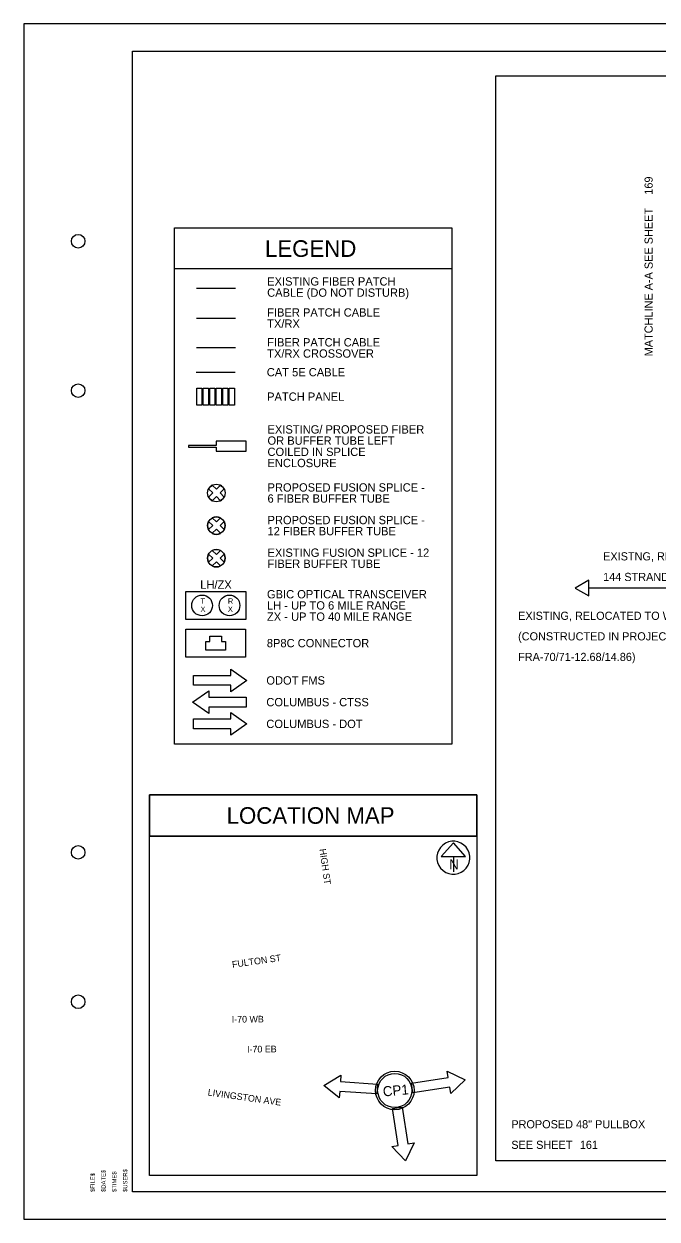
# Model space of a CAD drawing. Extents: x 1805893 to 1833564, y 708898 to 716199.
# Drawn here: x 1832103.1 to 1832336.4, y 713757.9 to 714197.9 of the extents above; entities that cross this region are included whole.
import ezdxf

# ---------------------------------------------------------------- set-up
doc = ezdxf.new("R2010")
doc.units = 0
for name, color, linetype in [('BR_P_Sub_Hidden', 7, 'Continuous'), ('BR_X_Slab_Object', 7, 'Continuous'), ('SH_Border', 7, 'Continuous'), ('SH_Cut_Line', 7, 'Continuous'), ('SH_Data', 7, 'Continuous'), ('SH_Text', 7, 'Continuous'), ('UT_X_Misc_Cells', 7, 'Continuous')]:
    doc.layers.add(name, color=color, linetype=linetype)

msp = doc.modelspace()

# ---------------------------------------------------------------- linework, layer by layer
at = {"layer": 'BR_P_Sub_Hidden'}
msp.add_lwpolyline([(1832277.01, 714178.75), (1832747.57, 714178.75), (1832747.57, 713779.36), (1832277.01, 713779.36)], close=True, dxfattribs=at)
at = {"layer": 'SH_Border'}
msp.add_lwpolyline([(1832143.13, 714187.91), (1832773.13, 714187.91), (1832773.13, 713767.91), (1832143.13, 713767.91)], close=True, dxfattribs=at)
for centre in [(1832123.13, 714117.91), (1832123.13, 714062.91), (1832123.13, 713892.91), (1832123.13, 713837.91)]:
    msp.add_circle(centre, 2.5, dxfattribs=at)
at = {"layer": 'SH_Cut_Line'}
msp.add_lwpolyline([(1832103.13, 713757.91), (1832783.13, 713757.91), (1832783.13, 714197.91), (1832103.13, 714197.91)], close=True, dxfattribs=at)
at = {"layer": 'SH_Data'}
for p, q in [((1832166.73, 714100.63), (1832181.07, 714100.63)), ((1832166.73, 714089.63), (1832181.07, 714089.63)), ((1832174.03, 714026.58), (1832172.54, 714028.08)), ((1832174.03, 714026.58), (1832172.54, 714028.08)), ((1832174.03, 714026.58), (1832175.53, 714028.08)), ((1832175.53, 714028.08), (1832174.03, 714026.58)), ((1832172.68, 714025.23), (1832171.19, 714026.72)), ((1832171.19, 714026.72), (1832172.68, 714025.23)), ((1832171.19, 714023.74), (1832172.68, 714025.23)), ((1832172.68, 714025.23), (1832171.19, 714023.74)), ((1832172.54, 714022.38), (1832174.03, 714023.87)), ((1832172.54, 714022.38), (1832174.03, 714023.87)), ((1832175.53, 714022.38), (1832174.03, 714023.87)), ((1832174.03, 714023.87), (1832175.53, 714022.38)), ((1832175.39, 714025.23), (1832176.88, 714026.72)), ((1832175.39, 714025.23), (1832176.88, 714026.72)), ((1832176.88, 714023.74), (1832175.39, 714025.23)), ((1832176.88, 714023.74), (1832175.39, 714025.23)), ((1832172.68, 714013.22), (1832171.19, 714014.71)), ((1832172.68, 714013.22), (1832171.19, 714014.71)), ((1832174.03, 714014.57), (1832172.54, 714016.07)), ((1832172.54, 714016.07), (1832174.03, 714014.57)), ((1832174.03, 714014.57), (1832175.53, 714016.07)), ((1832174.03, 714014.57), (1832175.53, 714016.07)), ((1832175.39, 714013.22), (1832176.88, 714014.71)), ((1832176.88, 714014.71), (1832175.39, 714013.22)), ((1832171.19, 714011.73), (1832172.68, 714013.22)), ((1832171.19, 714011.73), (1832172.68, 714013.22)), ((1832172.54, 714010.37), (1832174.03, 714011.86)), ((1832174.03, 714011.86), (1832172.54, 714010.37)), ((1832175.53, 714010.37), (1832174.03, 714011.86)), ((1832175.53, 714010.37), (1832174.03, 714011.86)), ((1832176.88, 714011.73), (1832175.39, 714013.22)), ((1832175.39, 714013.22), (1832176.88, 714011.73)), ((1832172.68, 714001.21), (1832171.19, 714002.71)), ((1832172.68, 714001.21), (1832171.19, 714002.71)), ((1832171.19, 713999.72), (1832172.68, 714001.21)), ((1832171.19, 713999.72), (1832172.68, 714001.21)), ((1832174.03, 714002.57), (1832172.54, 714004.06)), ((1832172.54, 714004.06), (1832174.03, 714002.57)), ((1832174.03, 714002.57), (1832175.53, 714004.06)), ((1832174.03, 714002.57), (1832175.53, 714004.06)), ((1832175.39, 714001.21), (1832176.88, 714002.71)), ((1832176.88, 714002.71), (1832175.39, 714001.21)), ((1832176.88, 713999.72), (1832175.39, 714001.21)), ((1832175.39, 714001.21), (1832176.88, 713999.72)), ((1832172.54, 713998.37), (1832174.03, 713999.86)), ((1832174.03, 713999.86), (1832172.54, 713998.37)), ((1832175.53, 713998.37), (1832174.03, 713999.86)), ((1832175.53, 713998.37), (1832174.03, 713999.86)), ((1832311.2, 713993.13), (1832306.18, 713990.23)), ((1832311.2, 713987.33), (1832311.2, 713993.13)), ((1832306.18, 713990.23), (1832311.2, 713987.33)), ((1832363.68, 713990.23), (1832311.2, 713990.23)), ((1832165.58, 713958.02), (1832179.31, 713958.02)), ((1832165.58, 713954.42), (1832165.58, 713958.02)), ((1832179.31, 713958.02), (1832179.31, 713960.42)), ((1832179.31, 713954.42), (1832165.58, 713954.42)), ((1832179.31, 713952.02), (1832179.31, 713954.42)), ((1832171.24, 713952.42), (1832171.24, 713950.02)), ((1832171.24, 713950.02), (1832184.98, 713950.02)), ((1832184.98, 713950.02), (1832184.98, 713946.42)), ((1832184.98, 713946.42), (1832171.24, 713946.42)), ((1832171.24, 713946.42), (1832171.24, 713944.02)), ((1832179.31, 713942.02), (1832179.31, 713944.42)), ((1832165.58, 713942.02), (1832179.31, 713942.02)), ((1832165.58, 713938.42), (1832165.58, 713942.02)), ((1832179.31, 713938.42), (1832165.58, 713938.42)), ((1832179.31, 713936.02), (1832179.31, 713938.42))]:
    msp.add_line(p, q, dxfattribs=at)
for points in [[(1832158.57, 714122.86), (1832260.8, 714122.86), (1832260.8, 714107.75), (1832158.57, 714107.75)], [(1832260.8, 714122.86), (1832260.8, 713932.7), (1832158.57, 713932.7), (1832158.57, 714122.86)], [(1832168.74, 714063.81), (1832168.74, 714057.56), (1832166.78, 714057.56), (1832166.78, 714063.81)], [(1832171.14, 714063.81), (1832171.14, 714057.56), (1832169.18, 714057.56), (1832169.18, 714063.81)], [(1832173.53, 714063.81), (1832173.53, 714057.56), (1832171.57, 714057.56), (1832171.57, 714063.81)], [(1832175.93, 714063.81), (1832175.93, 714057.56), (1832173.97, 714057.56), (1832173.97, 714063.81)], [(1832178.32, 714063.81), (1832178.32, 714057.56), (1832176.36, 714057.56), (1832176.36, 714063.81)], [(1832180.72, 714063.81), (1832180.72, 714057.56), (1832178.76, 714057.56), (1832178.76, 714063.81)], [(1832162.78, 713988.95), (1832184.88, 713988.95), (1832184.88, 713978.7), (1832162.78, 713978.7)], [(1832162.73, 713975.07), (1832184.82, 713975.07), (1832184.82, 713964.82), (1832162.73, 713964.82)], [(1832270.01, 713914.04), (1832149.37, 713914.04), (1832149.37, 713898.93), (1832270.01, 713898.93)], [(1832270.01, 713898.93), (1832149.37, 713898.93), (1832149.37, 713914.04), (1832270.01, 713914.04)], [(1832270.01, 713898.93), (1832270.01, 713773.91), (1832149.37, 713773.91), (1832149.37, 713898.93)], [(1832270.01, 713898.93), (1832270.01, 713773.91), (1832149.37, 713773.91), (1832149.37, 713898.93)], [(1832270.01, 713898.93), (1832270.01, 713773.91), (1832149.37, 713773.91), (1832149.37, 713898.93)]]:
    msp.add_lwpolyline(points, close=True, dxfattribs=at)
for points in [[(1832181.1, 714078.63), (1832166.73, 714078.63), (1832166.73, 714078.63), (1832166.73, 714078.63)], [(1832166.6, 714069.69), (1832180.94, 714069.72), (1832180.94, 714069.72)], [(1832163.74, 714042.75), (1832163.74, 714042.45), (1832163.74, 714042.14), (1832174.02, 714042.14), (1832174.02, 714040.61), (1832185.07, 714040.61), (1832185.07, 714044.28), (1832174.02, 714044.28), (1832174.02, 714042.75), (1832163.74, 714042.75)], [(1832185.07, 714040.61), (1832185.07, 714044.28), (1832174.02, 714044.28), (1832174.02, 714042.75), (1832163.74, 714042.75), (1832163.74, 714042.45), (1832163.74, 714042.14), (1832174.02, 714042.14), (1832174.02, 714040.61), (1832185.07, 714040.61)], [(1832175.9, 713970.55), (1832177.41, 713970.55), (1832177.41, 713967.32), (1832170.14, 713967.32), (1832170.14, 713970.55), (1832171.65, 713970.55)], [(1832171.65, 713970.55), (1832171.65, 713972.46), (1832175.9, 713972.46), (1832175.9, 713970.55)], [(1832179.31, 713960.42), (1832185.31, 713956.22), (1832179.31, 713952.02)], [(1832171.24, 713944.02), (1832165.24, 713948.22), (1832171.24, 713952.42)], [(1832179.31, 713944.42), (1832185.31, 713940.22), (1832179.31, 713936.02)]]:
    msp.add_lwpolyline(points, dxfattribs=at)
for centre, radius in [((1832174.03, 714025.23), 3.22), ((1832174.03, 714013.22), 3.22), ((1832174.03, 714001.21), 3.22), ((1832168.78, 713983.83), 3.81), ((1832178.88, 713983.83), 3.81)]:
    msp.add_circle(centre, radius, dxfattribs=at)
for centre, start, end in [((1832174.03, 714025.23), 117.647, 152.353), ((1832174.03, 714025.23), 27.647, 62.353), ((1832174.03, 714025.23), 207.647, 242.353), ((1832174.03, 714025.23), 297.647, 332.353), ((1832174.03, 714013.22), 152.353, 207.647), ((1832174.03, 714013.22), 62.353, 117.647), ((1832174.03, 714013.22), 332.353, 27.647), ((1832174.03, 714013.22), 242.353, 297.647), ((1832174.03, 714001.21), 152.353, 207.647), ((1832174.03, 714001.21), 62.353, 117.647), ((1832174.03, 714001.21), 332.353, 27.647), ((1832174.03, 714001.21), 242.353, 297.647)]:
    msp.add_arc(centre, 3.22, start, end, dxfattribs=at)
at = {"layer": 'SH_Text'}
for p, q in [((1832261.33, 713896.42), (1832256.83, 713891.42)), ((1832265.84, 713891.42), (1832261.33, 713896.42)), ((1832256.83, 713891.42), (1832265.84, 713891.42)), ((1832261.33, 713891.42), (1832261.33, 713885.76)), ((1832259.45, 713810.04), (1832259.08, 713812.41)), ((1832219.9, 713810.91), (1832219.74, 713808.51)), ((1832219.74, 713808.51), (1832233.44, 713807.58)), ((1832245.88, 713807.94), (1832259.45, 713810.04)), ((1832246.43, 713804.38), (1832245.88, 713807.94)), ((1832219.49, 713804.92), (1832219.33, 713802.53)), ((1832233.2, 713803.99), (1832219.49, 713804.92)), ((1832233.44, 713807.58), (1832233.2, 713803.99)), ((1832260, 713806.48), (1832246.43, 713804.38)), ((1832260.37, 713804.11), (1832260, 713806.48)), ((1832238.88, 713798.58), (1832242.44, 713799.14)), ((1832242.44, 713799.14), (1832244.54, 713785.56)), ((1832240.99, 713785.01), (1832238.88, 713798.58)), ((1832244.54, 713785.56), (1832246.92, 713785.93)), ((1832238.61, 713784.64), (1832240.99, 713785.01))]:
    msp.add_line(p, q, dxfattribs=at)
for points in [[(1832259.08, 713812.41), (1832265.66, 713809.18), (1832260.37, 713804.11)], [(1832219.33, 713802.53), (1832213.63, 713807.12), (1832219.9, 713810.91)], [(1832246.92, 713785.93), (1832243.69, 713779.36), (1832238.61, 713784.64)]]:
    msp.add_lwpolyline(points, dxfattribs=at)
for radius in [7.11, 6.31]:
    msp.add_circle((1832239.76, 713805.26), radius, dxfattribs=at)
msp.add_arc((1832261.33, 713890.95), 6.08, 129.7798, 129.7633, dxfattribs=at)

# ---------------------------------------------------------------- texts
at = {"layer": 'BR_X_Slab_Object'}
for s, height, rotation, p in [('169', 3, 90, (1832334.76, 714135.03)), ('T', 2, 0.0475, (1832168.17, 713984.43)), ('R', 2, 0.0475, (1832178.27, 713984.43)), ('X', 2, 0.0475, (1832168.18, 713981.43)), ('X', 2, 0.0475, (1832178.27, 713981.43))]:
    msp.add_text(s, height=height, rotation=rotation, dxfattribs=at).set_placement(p)
msp.add_text('161', height=3, dxfattribs=at).set_placement((1832307.91, 713783.75))
at = {"layer": 'SH_Data'}
msp.add_text('MATCHLINE A-A SEE SHEET', height=3, rotation=90, dxfattribs=at).set_placement((1832334.76, 714075.54))
for s, height, p in [('LEGEND', 6.119, (1832191.95, 714112.14)), ('EXISTING FIBER PATCH ', 3.0596, (1832192.75, 714101.58)), ('CABLE (DO NOT DISTURB)', 3.0596, (1832192.75, 714097.46)), ('TX/RX', 3.06, (1832192.75, 714086.04)), ('FIBER PATCH CABLE', 3.0596, (1832192.75, 714090.16)), ('FIBER PATCH CABLE', 3.0596, (1832192.75, 714079.16)), ('TX/RX CROSSOVER', 3.0596, (1832192.75, 714075.04)), ('CAT 5E CABLE', 3.0596, (1832192.61, 714068.16)), ('PATCH PANEL', 3.0596, (1832192.73, 714059.16)), ('EXISTING/ PROPOSED FIBER ', 3.0596, (1832192.87, 714047.1)), ('OR BUFFER TUBE LEFT ', 3.0596, (1832192.87, 714042.98)), ('COILED IN SPLICE ', 3.0596, (1832192.87, 714038.85)), ('ENCLOSURE', 3.06, (1832192.87, 714034.73)), ('PROPOSED FUSION SPLICE - ', 3.0596, (1832192.88, 714025.74)), ('6 FIBER BUFFER TUBE', 3.0596, (1832192.88, 714021.66)), ('PROPOSED FUSION SPLICE - ', 3.0596, (1832192.88, 714013.73)), ('12 FIBER BUFFER TUBE', 3.0596, (1832192.88, 714009.65)), ('EXISTING FUSION SPLICE - 12 ', 3.0596, (1832192.88, 714001.72)), ('EXISTNG, RELOCATED', 3, (1832316.5, 714000.4)), ('FIBER BUFFER TUBE', 3.0596, (1832192.88, 713997.65)), ('LH/ZX', 3.06, (1832168.1, 713989.95)), ('144 STRAND FOC', 3, (1832316.5, 713992.82)), ('GBIC OPTICAL TRANSCEIVER', 3.0596, (1832192.68, 713986.42)), ('LH - UP TO 6 MILE RANGE', 3.0596, (1832192.68, 713982.3)), ('ZX - UP TO 40 MILE RANGE', 3.0596, (1832192.68, 713978.17)), ('EXISTING, RELOCATED TO WEST', 3, (1832285.18, 713978.52)), ('8P8C CONNECTOR', 3.0596, (1832192.62, 713968.42)), ('(CONSTRUCTED IN PROJECT 4R - ', 3, (1832285.18, 713970.95)), ('FRA-70/71-12.68/14.86)', 3, (1832285.18, 713963.37)), ('ODOT FMS', 3.06, (1832192.45, 713954.69)), ('COLUMBUS - CTSS', 3.0596, (1832192.45, 713946.69)), ('COLUMBUS - DOT', 3.0596, (1832192.45, 713938.69)), ('LOCATION MAP', 6.1191, (1832177.82, 713903.43))]:
    msp.add_text(s, height=height, dxfattribs=at).set_placement(p)
at = {"layer": 'SH_Text'}
for s, height, rotation, p in [('HIGH ST', 2.448, 278.061, (1832211.97, 713894.08)), ('N', 3.66, 360, (1832259.81, 713886.68)), ('FULTON ST', 2.448, 8.061, (1832179.98, 713850.41)), ('I-70 WB', 2.448, 0.3445, (1832179.69, 713830.24)), ('I-70 EB', 2.448, 0.3445, (1832185.34, 713819.23)), ('LIVINGSTON AVE', 2.4477, 352.086, (1832170.75, 713803.41)), ('CP1', 3.671, 5, (1832235.52, 713803.04))]:
    msp.add_text(s, height=height, rotation=rotation, dxfattribs=at).set_placement(p)
for s, p in [('PROPOSED 48" PULLBOX', (1832282.68, 713791.33)), ('SEE SHEET', (1832282.68, 713783.75))]:
    msp.add_text(s, height=3, dxfattribs=at).set_placement(p)
at = {"layer": 'UT_X_Misc_Cells'}
for s, p in [('$FILE$', (1832129.23, 713767.91)), ('$DATE$', (1832133.23, 713767.91)), ('$TIME$', (1832137.23, 713767.91)), ('$USER$', (1832141.23, 713767.91))]:
    msp.add_text(s, height=1.56, rotation=90, dxfattribs=at).set_placement(p)

doc.saveas('drawing.dxf')
